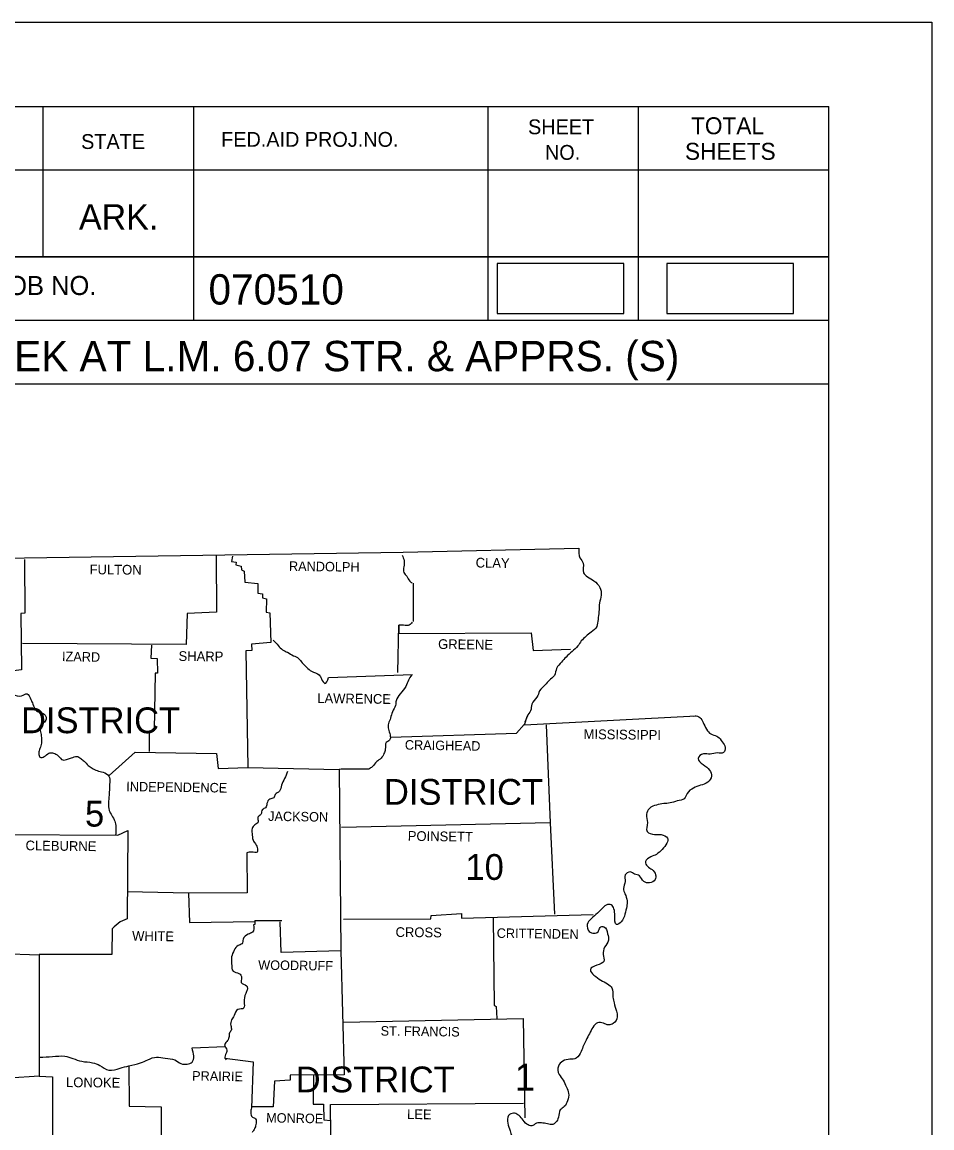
# Model space of a CAD drawing. Extents: x 1373094 to 1376427, y 1168361 to 1170494.
# Drawn here: x 1376007 to 1376427, y 1169984 to 1170494 of the extents above; entities that cross this region are included whole.
import ezdxf

# ---------------------------------------------------------------- set-up
doc = ezdxf.new("R2010")
doc.units = 0
for name, color, linetype in [('Default', 7, 'Continuous'), ('R_Border', 7, 'Continuous'), ('R_No Plot', 7, 'Continuous')]:
    doc.layers.add(name, color=color, linetype=linetype)

msp = doc.modelspace()

# ---------------------------------------------------------------- linework, layer by layer
at = {"layer": 'Default'}
for p, q in [((1376239.11, 1170170.11), (1376240.37, 1170173.97)), ((1376239.43, 1170171.36), (1376240.68, 1170174.39)), ((1376114.65, 1170079.69), (1376127.08, 1170079.69))]:
    msp.add_line(p, q, dxfattribs=at)
for points in [[(1376226.57, 1170359.93), (1376284.9, 1170359.93), (1376284.9, 1170383.03), (1376226.57, 1170383.03)], [(1376304.82, 1170359.93), (1376363.15, 1170359.93), (1376363.15, 1170383.03), (1376304.82, 1170383.03)]]:
    msp.add_lwpolyline(points, close=True, dxfattribs=at)
for points in [[(1375691.37, 1170246.85), (1375860.2, 1170246.75), (1376008.36, 1170247.06), (1376183.15, 1170249.77), (1376264.17, 1170251.65)], [(1376008.36, 1170246.43), (1376008.57, 1170221.58), (1376006.8, 1170221.48), (1376007.11, 1170195.48), (1375999.8, 1170194.44), (1376000.43, 1170187.44), (1376002.93, 1170184.21), (1376002.72, 1170175.96), (1375988.52, 1170175.44), (1375988, 1170162.7), (1375975.05, 1170162.28), (1375974.43, 1170146.83), (1375975.16, 1170145.57), (1375975.47, 1170120.93), (1375997.82, 1170119.47), (1375997.5, 1170064.45), (1376015.25, 1170063.93), (1376015.25, 1170007.96), (1376001.26, 1170006.92), (1376000.22, 1169994.6), (1375976.73, 1169994.49)], [(1376096.8, 1170248), (1376097.01, 1170222.11), (1376083.43, 1170221.38), (1376083.02, 1170207.18), (1376007.53, 1170207.59)], [(1376104.32, 1170247.9), (1376104, 1170245.39), (1376106.09, 1170245.08), (1376105.99, 1170243.82), (1376108.39, 1170243.3), (1376108.6, 1170241.63), (1376109.75, 1170240.9), (1376110.06, 1170235.89), (1376116.01, 1170235.26), (1376116.01, 1170230.77), (1376118.2, 1170230.46), (1376118.2, 1170228.68), (1376120.08, 1170228.16), (1376119.98, 1170222.11), (1376121.65, 1170221.79), (1376122.07, 1170208.12), (1376113.19, 1170207.28), (1376113.3, 1170204.36), (1376110.58, 1170204.25), (1376111.52, 1170150.38), (1376153.6, 1170149.44), (1376154.33, 1170065.7), (1376126.87, 1170064.97), (1376126.35, 1170079.07)], [(1376187.74, 1170235.37), (1376187.74, 1170217.72)], [(1376180.64, 1170194.23), (1376181.16, 1170216.05), (1376181.16, 1170212.19), (1376242.24, 1170212.5), (1376243.08, 1170204.36), (1376260.31, 1170204.98)], [(1376066.94, 1170206.86), (1376066.73, 1170200.81), (1376069.65, 1170200.6), (1376069.76, 1170193.92), (1376068.71, 1170193.92), (1376068.29, 1170167.6), (1376065.89, 1170166.56), (1376065.89, 1170157.79)], [(1376148.69, 1170191.93), (1376187.43, 1170193.29)], [(1376177.51, 1170164.37), (1376235.46, 1170166.25), (1376238.9, 1170170.21)], [(1376239.11, 1170170.11), (1376318.36, 1170174.18)], [(1376249.14, 1170170.01), (1376250.91, 1170124.8), (1376253, 1170082.72)], [(1376047.52, 1170146.62), (1376059.42, 1170157.37), (1376097.01, 1170156.85), (1376097.74, 1170149.85), (1376111.42, 1170150.38)], [(1376167.28, 1170149.65), (1376154.54, 1170149.65), (1376153.6, 1170149.44)], [(1376250.91, 1170124.8), (1376154.75, 1170122.6)], [(1375997.82, 1170119.47), (1376051.48, 1170119.16), (1376056.08, 1170121.35), (1376055.77, 1170080.53), (1376052.63, 1170079.17), (1376049.81, 1170076.77), (1376048.87, 1170075.83), (1376048.77, 1170064.13), (1376015.25, 1170064.13)], [(1376111, 1170110.91), (1376111.21, 1170092.53), (1376084.06, 1170092.43), (1376055.86, 1170092.96)], [(1376084.06, 1170092.43), (1376084.48, 1170078.75), (1376114.65, 1170079.29)], [(1376155.58, 1170080.32), (1376195.89, 1170080.53), (1376195.99, 1170081.99), (1376209.98, 1170083.03), (1376209.98, 1170080.84), (1376270.75, 1170082.51)], [(1376114.65, 1170079.69), (1376114.65, 1170077.92), (1376114.13, 1170077.81)], [(1376224.6, 1170080.84), (1376225.12, 1170040.64), (1376226.06, 1170040.02), (1376226.37, 1170034.59)], [(1376224.6, 1170080.84), (1376225.12, 1170040.64), (1376226.06, 1170040.02), (1376226.37, 1170034.59)], [(1376224.6, 1170080.84), (1376225.12, 1170040.64), (1376226.06, 1170040.02), (1376226.37, 1170034.59)], [(1376224.6, 1170080.84), (1376225.12, 1170040.64), (1376226.06, 1170040.02), (1376226.37, 1170034.59)], [(1376224.6, 1170080.84), (1376225.12, 1170040.64), (1376226.06, 1170040.02), (1376226.37, 1170034.59)], [(1376154.33, 1170065.7), (1376155.9, 1170008.48), (1376131.05, 1170008.38), (1376130.94, 1170006.08), (1376123.74, 1170005.67), (1376123.11, 1169993.76), (1376113.21, 1169993.76)], [(1376155.58, 1170032.81), (1376238.49, 1170034.48)], [(1376238.49, 1170034.48), (1376239.32, 1169988.75)], [(1376238.49, 1170034.48), (1376239.32, 1169988.75)], [(1376238.49, 1170034.48), (1376239.32, 1169988.75)], [(1376238.49, 1170034.48), (1376239.32, 1169988.75)], [(1376238.49, 1170034.48), (1376239.32, 1169988.75)], [(1376238.49, 1170034.48), (1376239.32, 1169988.75)], [(1376238.49, 1170034.48), (1376239.32, 1169988.75)], [(1376238.49, 1170034.48), (1376239.32, 1169988.75)], [(1376085.73, 1170020.91), (1376100.97, 1170021.65)], [(1376056.5, 1170012.77), (1376056.7, 1169994.08), (1376071.43, 1169993.76), (1376071.53, 1169953.67)], [(1376100.87, 1170016.21), (1376113.92, 1170014.54), (1376113.19, 1169993.24)], [(1376015.25, 1170007.96), (1376021.31, 1170007.55), (1376021.41, 1169967.66), (1376015.98, 1169945), (1376027.57, 1169944.48), (1376027.47, 1169924.53)], [(1376141.7, 1170008.43), (1376141.59, 1169994.91), (1376146.39, 1169994.91), (1376146.6, 1169987.71), (1376149.69, 1169987.39)], [(1376153.99, 1169902.2), (1376163.73, 1169902.82), (1376163.62, 1169924.02), (1376156, 1169924.54), (1376156.42, 1169965.99), (1376149.84, 1169966.93), (1376149.63, 1169994.81), (1376238.69, 1169995.43)]]:
    msp.add_lwpolyline(points, dxfattribs=at)
for points in [[(1376264.17, 1170251.65), (1376264.69, 1170247.06), (1376266.16, 1170244.66), (1376266.36, 1170240.27), (1376268.14, 1170238.39), (1376271.17, 1170236.51), (1376273.88, 1170233.49), (1376274.51, 1170229.94), (1376273.67, 1170226.28), (1376273.46, 1170222.21), (1376273.05, 1170218.66), (1376272.42, 1170215.42), (1376269.91, 1170212.81), (1376267.51, 1170210.93), (1376265.32, 1170208.74), (1376263.75, 1170206.44), (1376261.04, 1170203.94), (1376258.32, 1170201.33), (1376256.13, 1170199.03), (1376253.94, 1170196.11), (1376252.89, 1170192.87), (1376250.49, 1170190.57), (1376248.61, 1170188.49), (1376246.11, 1170185.67), (1376244.86, 1170182.85), (1376242.45, 1170179.61), (1376241.93, 1170176.48), (1376240.37, 1170173.97), (1376240.26, 1170173.56)], [(1376182.63, 1170248.42), (1376183.57, 1170245.81), (1376183.46, 1170242.99), (1376183.46, 1170240.38), (1376184.82, 1170238.6), (1376186.18, 1170236.41), (1376187.22, 1170235.47)], [(1376187.32, 1170217.41), (1376185.97, 1170216.05), (1376183.36, 1170216.05), (1376181.16, 1170216.05)], [(1376123.22, 1170209.05), (1376125.51, 1170206.65), (1376127.5, 1170204.67), (1376129.79, 1170203.52), (1376132.51, 1170201.96), (1376134.91, 1170200.7), (1376136.48, 1170198.72), (1376138.67, 1170196.53), (1376140.86, 1170194.75), (1376144.31, 1170193.08), (1376145.45, 1170191.31), (1376147.02, 1170189.11), (1376148.69, 1170191.93)], [(1376187.12, 1170193.18), (1376185.55, 1170190.68), (1376184.3, 1170187.76), (1376181.79, 1170184.41), (1376179.91, 1170181.18), (1376179.6, 1170178.99), (1376178.14, 1170176.06), (1376177.3, 1170173.14), (1376176.36, 1170170.63), (1376176.36, 1170168.02), (1376177.09, 1170165.41), (1376176.88, 1170163.01), (1376175.32, 1170161.86), (1376174.9, 1170158.83), (1376174.27, 1170156.75), (1376172.92, 1170154.66), (1376170.93, 1170153.09), (1376168.84, 1170150.69), (1376167.28, 1170149.65)], [(1376002.93, 1170184.21), (1376007.11, 1170183.47), (1376009.62, 1170184.41), (1376011.39, 1170181.7), (1376012.33, 1170179.61), (1376013.9, 1170176.58), (1376016.4, 1170175.64), (1376018.28, 1170173.97), (1376018.28, 1170172.2), (1376016.61, 1170170.53), (1376015.36, 1170168.86), (1376015.78, 1170166.87), (1376016.19, 1170164.16), (1376016.19, 1170161.55), (1376015.57, 1170159.15), (1376015.04, 1170156.95), (1376015.57, 1170155.08), (1376017.55, 1170155.39), (1376019.64, 1170156.95), (1376021.83, 1170156.95), (1376023.92, 1170155.81), (1376026.11, 1170153.82), (1376028.3, 1170154.24), (1376030.08, 1170154.76), (1376032.59, 1170155.49), (1376034.36, 1170154.55), (1376035.93, 1170153.3), (1376037.81, 1170151.32), (1376039.58, 1170150.06), (1376041.88, 1170148.92), (1376044.7, 1170148.18), (1376047.31, 1170146.41), (1376047.73, 1170143.38), (1376047.62, 1170140.77), (1376047.41, 1170137.53), (1376047.2, 1170133.98), (1376047.52, 1170130.54), (1376048.67, 1170128.24), (1376050.13, 1170125.53), (1376050.54, 1170123.02), (1376050.44, 1170119.05)], [(1376317.21, 1170174.08), (1376318.36, 1170174.18), (1376321.91, 1170170.42), (1376323.48, 1170167.29), (1376325.77, 1170165.52), (1376328.38, 1170164.58), (1376330.37, 1170162.18), (1376331.73, 1170159.56), (1376330.99, 1170157.27), (1376328.07, 1170157.06), (1376324.83, 1170156.54), (1376321.7, 1170156.64), (1376319.2, 1170154.55), (1376321.49, 1170151.73), (1376324.52, 1170149.12), (1376325.36, 1170146.3), (1376323.69, 1170143.59), (1376320.34, 1170142.13), (1376317.11, 1170140.88), (1376314.18, 1170138.37), (1376312.83, 1170135.97), (1376309.59, 1170134.92), (1376306.25, 1170133.98), (1376303.33, 1170133.67), (1376299.98, 1170133.04), (1376296.75, 1170131.48), (1376295.39, 1170128.76), (1376295.81, 1170124.9), (1376295.7, 1170120.83), (1376299.15, 1170119.47), (1376302.18, 1170119.37), (1376305.1, 1170117.8), (1376304.79, 1170115.5), (1376302.59, 1170112.58), (1376299.98, 1170110.28), (1376297.37, 1170109.14), (1376294.97, 1170106.94), (1376295.81, 1170104.75), (1376298, 1170103.29), (1376299.57, 1170100.89), (1376299.36, 1170098.69), (1376296.85, 1170097.13), (1376294.14, 1170097.75), (1376292.15, 1170100.36), (1376289.86, 1170101.2), (1376287.87, 1170102.14), (1376285.58, 1170100.78), (1376285.58, 1170097.75), (1376284.74, 1170094.52), (1376285.47, 1170092.12), (1376286.41, 1170088.78), (1376286.31, 1170086.27), (1376285.47, 1170082.72), (1376283.7, 1170079.07), (1376281.61, 1170077.92), (1376280.77, 1170081.88), (1376280.36, 1170085.12), (1376279.1, 1170087), (1376277.43, 1170087.1), (1376275.24, 1170085.54), (1376272.84, 1170083.14), (1376269.81, 1170080.53), (1376268.03, 1170077.92), (1376268.97, 1170074.68), (1376271.27, 1170073.84), (1376273.05, 1170074.47), (1376273.99, 1170076.56), (1376275.76, 1170076.87), (1376277.43, 1170073.64)], [(1376129.69, 1170148.5), (1376128.44, 1170145.26), (1376126.97, 1170142.13), (1376126.03, 1170139.41), (1376124.05, 1170137.85), (1376123.42, 1170136.39), (1376121.65, 1170135.76), (1376120.29, 1170133.67), (1376119.67, 1170131.79), (1376118.2, 1170130.96), (1376117.47, 1170128.66), (1376116.12, 1170127.41), (1376116.22, 1170125.32), (1376114.65, 1170123.86), (1376113.4, 1170122.19), (1376113.4, 1170119.89), (1376113.92, 1170116.86), (1376114.97, 1170115.09), (1376115.91, 1170112.79), (1376115.8, 1170111.33), (1376113.19, 1170111.33), (1376111, 1170110.91)], [(1376114.13, 1170077.81), (1376113.61, 1170074.37), (1376111.63, 1170073.43), (1376109.33, 1170071.13), (1376108.81, 1170069.04), (1376106.93, 1170068.21), (1376105.15, 1170066.01), (1376104, 1170062.99), (1376104, 1170059.85), (1376104.73, 1170056.3), (1376107.34, 1170055.36), (1376108.6, 1170053.28), (1376108.39, 1170051.08), (1376110.89, 1170049.62), (1376111.31, 1170048.37), (1376110.89, 1170047.01), (1376109.75, 1170043.15), (1376109.85, 1170040.54), (1376109.64, 1170039.39), (1376106.82, 1170038.66), (1376105.15, 1170035.84), (1376104, 1170033.86), (1376103.59, 1170031.25), (1376103.9, 1170029.37), (1376103.06, 1170027.9), (1376102.75, 1170025.71), (1376101.71, 1170023.83), (1376100.77, 1170022.06), (1376101.81, 1170019.97), (1376101.5, 1170018.51), (1376100.87, 1170016.21), (1376101.39, 1170015.48)], [(1376277.43, 1170073.64), (1376277.85, 1170070.61), (1376276.07, 1170067.37), (1376275.45, 1170064.13), (1376275.76, 1170060.9), (1376272.42, 1170059.12), (1376269.5, 1170057.04), (1376271.17, 1170054.53), (1376274.3, 1170052.23), (1376277.43, 1170050.46), (1376279.42, 1170048.68), (1376279.94, 1170044.4), (1376280.46, 1170041.69), (1376281.5, 1170037.93), (1376281.92, 1170035.32), (1376280.04, 1170032.19), (1376277.85, 1170031.56), (1376275.55, 1170032.29), (1376272.84, 1170032.5), (1376270.64, 1170030.41), (1376269.08, 1170027.49), (1376267.51, 1170024.56), (1376266.36, 1170022.06), (1376265.22, 1170019.34), (1376262.92, 1170016.21), (1376260.1, 1170015.69), (1376256.76, 1170014.85), (1376254.77, 1170012.56), (1376255.09, 1170008.69), (1376256.97, 1170006.08), (1376258.43, 1170002.85), (1376259.47, 1170000.03), (1376258.95, 1169996.48), (1376257.49, 1169993.87), (1376255.61, 1169992.3), (1376254.77, 1169988.96), (1376253.42, 1169986.45), (1376252.16, 1169985.62), (1376249.66, 1169985.83), (1376246.94, 1169986.35), (1376244.65, 1169986.14), (1376242.45, 1169984.99), (1376240.26, 1169985.72), (1376237.96, 1169988.23), (1376236.08, 1169990.11), (1376234, 1169990.84), (1376231.8, 1169989.69), (1376231.39, 1169986.25), (1376232.43, 1169982.7), (1376233.37, 1169977.89), (1376232.43, 1169974.97), (1376232.12, 1169970.17)], [(1376015.46, 1170016.73), (1376021.31, 1170016.94), (1376027.05, 1170017.15), (1376030.71, 1170016.11), (1376034.88, 1170014.75), (1376039.79, 1170014.12), (1376043.24, 1170012.77), (1376047.31, 1170010.68), (1376052.53, 1170011.62), (1376056.6, 1170012.66), (1376061.93, 1170014.02), (1376065.37, 1170015.48), (1376069.34, 1170016.73), (1376073.31, 1170016.21), (1376077.8, 1170015.38), (1376080.62, 1170013.71), (1376085.73, 1170014.44), (1376085.73, 1170020.91)], [(1376113.19, 1169993.24), (1376112.77, 1169991.15), (1376113.61, 1169988.96), (1376115.07, 1169988.23), (1376115.28, 1169986.14), (1376114.76, 1169984.05), (1376114.34, 1169983.22), (1376113.4, 1169981.96)]]:
    msp.add_spline(points, degree=3, dxfattribs=at)
at = {"layer": 'R_Border'}
for p, q in [((1373217.75, 1170455.42), (1376379.55, 1170455.42)), ((1376016.95, 1170455.42), (1376016.95, 1170386.02)), ((1376086.35, 1170455.42), (1376086.35, 1170356.62)), ((1376222.15, 1170455.42), (1376222.15, 1170356.62)), ((1376291.55, 1170455.42), (1376291.55, 1170356.62)), ((1376379.55, 1168400.82), (1376379.55, 1170455.42)), ((1376379.55, 1170426.02), (1375948.55, 1170426.02)), ((1376379.55, 1170426.22), (1376379.55, 1170426.22)), ((1376379.55, 1170386.02), (1375948.55, 1170386.02)), ((1375978.15, 1170386.02), (1376379.55, 1170386.02)), ((1376379.55, 1170356.62), (1375556.95, 1170356.62)), ((1375948.55, 1170327.42), (1376379.55, 1170327.42))]:
    msp.add_line(p, q, dxfattribs=at)
at = {"layer": 'R_No Plot'}
msp.add_line((1373093.74, 1170494.36), (1376427.07, 1170494.36), dxfattribs=at)
msp.add_lwpolyline([(1373093.67, 1170494.36), (1376427.07, 1170494.36), (1376427.07, 1168360.99), (1373093.67, 1168360.99)], close=True, dxfattribs=at)

# ---------------------------------------------------------------- texts
at = {"layer": 'Default'}
for s, height, rotation, p in [('CLAY', 4.489, 359.2258, (1376216.56, 1170242.67)), ('FULTON', 4.489, 359.4996, (1376038.43, 1170239.54)), ('RANDOLPH', 4.386, 359.2584, (1376130.42, 1170241.11)), ('GREENE', 4.49, 359.2361, (1376199.23, 1170205.09)), ('IZARD', 4.385, 358.9259, (1376025.69, 1170199.45)), ('SHARP', 4.489, 359.3905, (1376079.47, 1170199.55)), ('LAWRENCE', 4.49, 359.2678, (1376143.47, 1170180.13)), ('MISSISSIPPI', 4.4891, 359.3097, (1376266.36, 1170163.53)), ('CRAIGHEAD', 4.386, 359.1159, (1376183.88, 1170158.63)), ('INDEPENDENCE', 4.3845, 359.2188, (1376055.35, 1170139.41)), ('JACKSON', 4.384, 359.1352, (1376120.81, 1170125.74)), ('POINSETT', 4.489, 359.1987, (1376185.24, 1170116.55)), ('CLEBURNE', 4.489, 359.2535, (1376008.88, 1170112.16)), ('WHITE', 4.49, 359.3139, (1376058.06, 1170070.4)), ('CROSS', 4.489, 359.384, (1376179.6, 1170072.17)), ('CRITTENDEN', 4.386, 359.213, (1376226.27, 1170071.76)), ('WOODRUFF', 4.384, 359.2748, (1376116.22, 1170057.04)), ('ST. FRANCIS', 4.3845, 359.2216, (1376172.71, 1170026.65)), ('LONOKE', 4.49, 359.4974, (1376027.57, 1170002.85)), ('PRAIRIE', 4.386, 359.2116, (1376085.73, 1170005.87)), ('MONROE', 4.384, 359.0331, (1376119.87, 1169986.56)), ('LEE', 4.49, 359.4327, (1376184.92, 1169988.12))]:
    msp.add_text(s, height=height, rotation=rotation, dxfattribs=at).set_placement(p)
for s, height, p in [('DISTRICT', 11.903, (1376006.81, 1170166.19)), ('DISTRICT', 11.903, (1376174.27, 1170133.15)), ('5', 11.9, (1376036.33, 1170123.09)), ('10', 11.903, (1376211.89, 1170098.49)), ('DISTRICT', 11.903, (1376133.55, 1170000.45)), ('1', 12.53, (1376234.62, 1170001.18))]:
    msp.add_text(s, height=height, dxfattribs=at).set_placement(p)
at = {"layer": 'R_Border'}
for s, height, p in [('TOTAL', 7.819, (1376315.95, 1170442.62)), ('SHEET', 6.84, (1376240.75, 1170442.62)), ('STATE', 6.84, (1376034.55, 1170435.82)), ('FED.AID PROJ.NO.', 6.84, (1376099.15, 1170436.82)), ('NO.', 6.84, (1376248.55, 1170430.82)), ('SHEETS', 7.819, (1376313.15, 1170430.82)), ('ARK.', 11.723, (1376033.55, 1170398.62)), ('JOB NO.', 8.792, (1375994.55, 1170368.42)), ('070510', 14, (1376093.31, 1170364.01)), ('CREEK AT L.M. 6.07 STR. & APPRS. (S)', 14, (1375964.12, 1170333.25))]:
    msp.add_text(s, height=height, dxfattribs=at).set_placement(p)

doc.saveas('drawing.dxf')
